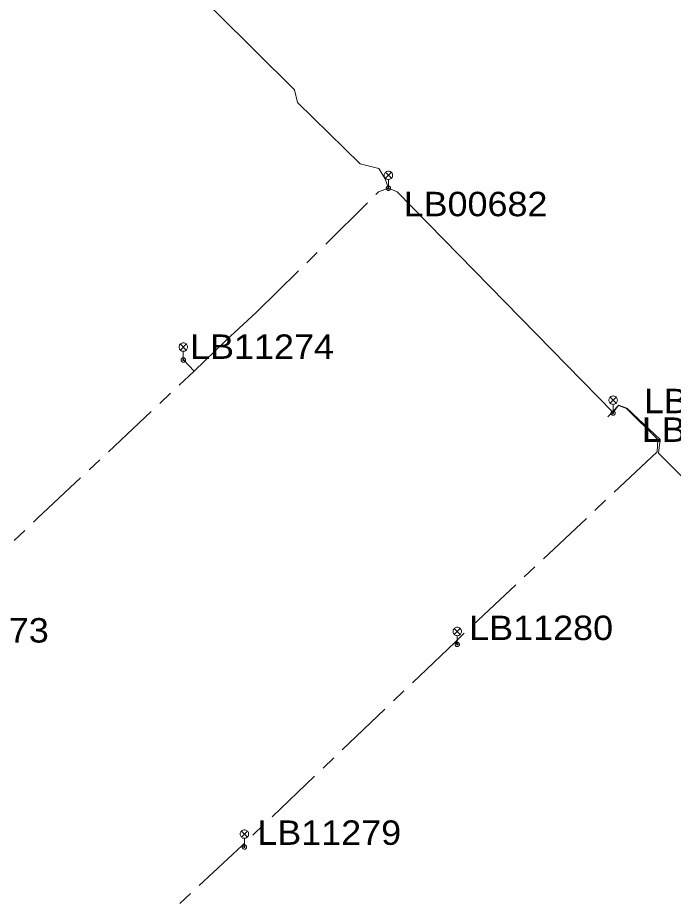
# Model space of a CAD drawing. Extents: x -688049 to -687261, y -973611 to -973038.
# Drawn here: x -687587.9 to -687529.7, y -973546.5 to -973468.5 of the extents above; entities that cross this region are included whole.
import ezdxf

# ---------------------------------------------------------------- set-up
doc = ezdxf.new("R2010")
doc.units = 0
doc.header["$LTSCALE"] = 0.87
doc.linetypes.add('LONG_DASH_SHORT_DASH', pattern=[9.9, 6, -1.2, 1.5, -1.2])
doc.layers.add('1', color=7, linetype='Continuous', lineweight=13)

msp = doc.modelspace()

# ---------------------------------------------------------------- linework, layer by layer
at = {"layer": '1'}
for p, q in [((-687555.305, -973482.205), (-687554.775, -973482.735)), ((-687555.305, -973482.735), (-687554.775, -973482.205)), ((-687555.04, -973483.62), (-687555.04, -973482.845)), ((-687573.504, -973497.442), (-687572.974, -973497.972)), ((-687573.504, -973497.972), (-687572.974, -973497.442)), ((-687573.239, -973498.857), (-687573.239, -973498.082)), ((-687535.365, -973502.155), (-687534.835, -973502.685)), ((-687535.365, -973502.685), (-687534.835, -973502.155)), ((-687535.1, -973503.57), (-687535.1, -973502.795)), ((-687549.195, -973522.675), (-687548.665, -973523.205)), ((-687549.195, -973523.205), (-687548.665, -973522.675)), ((-687548.93, -973524.09), (-687548.93, -973523.315)), ((-687568.084, -973540.652), (-687567.554, -973541.182)), ((-687568.084, -973541.182), (-687567.554, -973540.652)), ((-687567.819, -973542.067), (-687567.819, -973541.292))]:
    msp.add_line(p, q, dxfattribs=at)
at = {"layer": '1', "linetype": 'LONG_DASH_SHORT_DASH'}
for p, q in [((-687572.29, -973499.85), (-687573.23, -973498.85)), ((-687572.29, -973499.85), (-687573.23, -973498.85)), ((-687572.29, -973499.85), (-687573.23, -973498.85)), ((-687572.29, -973499.85), (-687573.23, -973498.85)), ((-687572.29, -973499.85), (-687573.23, -973498.85)), ((-687572.29, -973499.85), (-687573.23, -973498.85)), ((-687572.29, -973499.85), (-687573.23, -973498.85)), ((-687572.29, -973499.85), (-687573.23, -973498.85)), ((-687549.13, -973523.88), (-687568.01, -973541.92)), ((-687549.13, -973523.88), (-687568.01, -973541.92)), ((-687549.13, -973523.88), (-687568.01, -973541.92)), ((-687549.13, -973523.88), (-687568.01, -973541.92)), ((-687549.13, -973523.88), (-687568.01, -973541.92)), ((-687549.13, -973523.88), (-687568.01, -973541.92)), ((-687549.13, -973523.88), (-687568.01, -973541.92)), ((-687549.13, -973523.88), (-687568.01, -973541.92)), ((-687548.93, -973524.09), (-687549.13, -973523.88)), ((-687548.93, -973524.09), (-687549.13, -973523.88)), ((-687548.93, -973524.09), (-687549.13, -973523.88)), ((-687548.93, -973524.09), (-687549.13, -973523.88)), ((-687548.93, -973524.09), (-687549.13, -973523.88)), ((-687548.93, -973524.09), (-687549.13, -973523.88)), ((-687548.93, -973524.09), (-687549.13, -973523.88)), ((-687548.93, -973524.09), (-687549.13, -973523.88)), ((-687567.81, -973542.06), (-687568.01, -973541.92)), ((-687567.81, -973542.06), (-687568.01, -973541.92)), ((-687567.81, -973542.06), (-687568.01, -973541.92)), ((-687567.81, -973542.06), (-687568.01, -973541.92)), ((-687567.81, -973542.06), (-687568.01, -973541.92)), ((-687567.81, -973542.06), (-687568.01, -973541.92)), ((-687567.81, -973542.06), (-687568.01, -973541.92)), ((-687567.81, -973542.06), (-687568.01, -973541.92))]:
    msp.add_line(p, q, dxfattribs=at)
at = {"layer": '1'}
for points in [[(-687573.92, -973464.67), (-687573.727, -973464.6), (-687563.369, -973474.889), (-687563.105, -973476.008), (-687557.547, -973481.454), (-687555.888, -973481.862), (-687555.339, -973482.791), (-687555.04, -973483.62)], [(-687555.04, -973483.62), (-687554.25, -973483.935), (-687535.1, -973503.52)], [(-687535.096, -973503.52), (-687534.622, -973502.856), (-687533.88, -973503.123), (-687530.924, -973505.899), (-687531.06, -973507.111), (-687517.877, -973520.244), (-687517.442, -973520.985), (-687517.645, -973521.334)]]:
    msp.add_lwpolyline(points, dxfattribs=at)
for points in [[(-687554.665, -973482.47), (-687554.671, -973482.405), (-687554.688, -973482.342), (-687554.715, -973482.283), (-687554.753, -973482.229), (-687554.799, -973482.183), (-687554.852, -973482.145), (-687554.912, -973482.118), (-687554.975, -973482.101), (-687555.04, -973482.095), (-687555.105, -973482.101), (-687555.168, -973482.118), (-687555.228, -973482.145), (-687555.281, -973482.183), (-687555.327, -973482.229), (-687555.365, -973482.283), (-687555.392, -973482.342), (-687555.409, -973482.405), (-687555.415, -973482.47), (-687555.409, -973482.535), (-687555.392, -973482.598), (-687555.365, -973482.658), (-687555.327, -973482.711), (-687555.281, -973482.757), (-687555.228, -973482.795), (-687555.168, -973482.822), (-687555.105, -973482.839), (-687555.04, -973482.845), (-687554.975, -973482.839), (-687554.912, -973482.822), (-687554.852, -973482.795), (-687554.799, -973482.757), (-687554.753, -973482.711), (-687554.715, -973482.658), (-687554.688, -973482.598), (-687554.671, -973482.535)], [(-687554.85, -973483.62), (-687554.853, -973483.587), (-687554.861, -973483.555), (-687554.875, -973483.525), (-687554.894, -973483.498), (-687554.918, -973483.474), (-687554.945, -973483.455), (-687554.975, -973483.441), (-687555.007, -973483.433), (-687555.04, -973483.43), (-687555.073, -973483.433), (-687555.105, -973483.441), (-687555.135, -973483.455), (-687555.162, -973483.474), (-687555.186, -973483.498), (-687555.205, -973483.525), (-687555.219, -973483.555), (-687555.227, -973483.587), (-687555.23, -973483.62), (-687555.227, -973483.653), (-687555.219, -973483.685), (-687555.205, -973483.715), (-687555.186, -973483.742), (-687555.162, -973483.766), (-687555.135, -973483.785), (-687555.105, -973483.799), (-687555.073, -973483.807), (-687555.04, -973483.81), (-687555.007, -973483.807), (-687554.975, -973483.799), (-687554.945, -973483.785), (-687554.918, -973483.766), (-687554.894, -973483.742), (-687554.875, -973483.715), (-687554.861, -973483.685), (-687554.853, -973483.653)], [(-687554.99, -973483.62), (-687554.991, -973483.611), (-687554.993, -973483.603), (-687554.997, -973483.595), (-687555.002, -973483.588), (-687555.008, -973483.582), (-687555.015, -973483.577), (-687555.023, -973483.573), (-687555.031, -973483.571), (-687555.04, -973483.57), (-687555.049, -973483.571), (-687555.057, -973483.573), (-687555.065, -973483.577), (-687555.072, -973483.582), (-687555.078, -973483.588), (-687555.083, -973483.595), (-687555.087, -973483.603), (-687555.089, -973483.611), (-687555.09, -973483.62), (-687555.089, -973483.629), (-687555.087, -973483.637), (-687555.083, -973483.645), (-687555.078, -973483.652), (-687555.072, -973483.658), (-687555.065, -973483.663), (-687555.057, -973483.667), (-687555.049, -973483.669), (-687555.04, -973483.67), (-687555.031, -973483.669), (-687555.023, -973483.667), (-687555.015, -973483.663), (-687555.008, -973483.658), (-687555.002, -973483.652), (-687554.997, -973483.645), (-687554.993, -973483.637), (-687554.991, -973483.629)], [(-687572.864, -973497.707), (-687572.87, -973497.642), (-687572.887, -973497.579), (-687572.914, -973497.519), (-687572.952, -973497.466), (-687572.998, -973497.42), (-687573.052, -973497.382), (-687573.111, -973497.355), (-687573.174, -973497.338), (-687573.239, -973497.332), (-687573.304, -973497.338), (-687573.367, -973497.355), (-687573.426, -973497.382), (-687573.48, -973497.42), (-687573.526, -973497.466), (-687573.564, -973497.519), (-687573.591, -973497.579), (-687573.608, -973497.642), (-687573.614, -973497.707), (-687573.608, -973497.772), (-687573.591, -973497.835), (-687573.564, -973497.894), (-687573.526, -973497.948), (-687573.48, -973497.994), (-687573.426, -973498.032), (-687573.367, -973498.059), (-687573.304, -973498.076), (-687573.239, -973498.082), (-687573.174, -973498.076), (-687573.111, -973498.059), (-687573.052, -973498.032), (-687572.998, -973497.994), (-687572.952, -973497.948), (-687572.914, -973497.894), (-687572.887, -973497.835), (-687572.87, -973497.772)], [(-687573.049, -973498.857), (-687573.052, -973498.824), (-687573.06, -973498.792), (-687573.074, -973498.762), (-687573.093, -973498.735), (-687573.117, -973498.711), (-687573.144, -973498.692), (-687573.174, -973498.678), (-687573.206, -973498.67), (-687573.239, -973498.667), (-687573.272, -973498.67), (-687573.304, -973498.678), (-687573.334, -973498.692), (-687573.361, -973498.711), (-687573.385, -973498.735), (-687573.404, -973498.762), (-687573.418, -973498.792), (-687573.426, -973498.824), (-687573.429, -973498.857), (-687573.426, -973498.89), (-687573.418, -973498.922), (-687573.404, -973498.952), (-687573.385, -973498.979), (-687573.361, -973499.003), (-687573.334, -973499.022), (-687573.304, -973499.036), (-687573.272, -973499.044), (-687573.239, -973499.047), (-687573.206, -973499.044), (-687573.174, -973499.036), (-687573.144, -973499.022), (-687573.117, -973499.003), (-687573.093, -973498.979), (-687573.074, -973498.952), (-687573.06, -973498.922), (-687573.052, -973498.89)], [(-687573.189, -973498.857), (-687573.19, -973498.848), (-687573.192, -973498.84), (-687573.196, -973498.832), (-687573.201, -973498.825), (-687573.207, -973498.819), (-687573.214, -973498.814), (-687573.222, -973498.81), (-687573.23, -973498.808), (-687573.239, -973498.807), (-687573.248, -973498.808), (-687573.256, -973498.81), (-687573.264, -973498.814), (-687573.271, -973498.819), (-687573.277, -973498.825), (-687573.282, -973498.832), (-687573.286, -973498.84), (-687573.288, -973498.848), (-687573.289, -973498.857), (-687573.288, -973498.866), (-687573.286, -973498.874), (-687573.282, -973498.882), (-687573.277, -973498.889), (-687573.271, -973498.895), (-687573.264, -973498.9), (-687573.256, -973498.904), (-687573.248, -973498.906), (-687573.239, -973498.907), (-687573.23, -973498.906), (-687573.222, -973498.904), (-687573.214, -973498.9), (-687573.207, -973498.895), (-687573.201, -973498.889), (-687573.196, -973498.882), (-687573.192, -973498.874), (-687573.19, -973498.866)], [(-687534.725, -973502.42), (-687534.731, -973502.355), (-687534.748, -973502.292), (-687534.775, -973502.232), (-687534.813, -973502.179), (-687534.859, -973502.133), (-687534.912, -973502.095), (-687534.972, -973502.068), (-687535.035, -973502.051), (-687535.1, -973502.045), (-687535.165, -973502.051), (-687535.228, -973502.068), (-687535.288, -973502.095), (-687535.341, -973502.133), (-687535.387, -973502.179), (-687535.425, -973502.232), (-687535.452, -973502.292), (-687535.469, -973502.355), (-687535.475, -973502.42), (-687535.469, -973502.485), (-687535.452, -973502.548), (-687535.425, -973502.607), (-687535.387, -973502.661), (-687535.341, -973502.707), (-687535.288, -973502.745), (-687535.228, -973502.772), (-687535.165, -973502.789), (-687535.1, -973502.795), (-687535.035, -973502.789), (-687534.972, -973502.772), (-687534.912, -973502.745), (-687534.859, -973502.707), (-687534.813, -973502.661), (-687534.775, -973502.607), (-687534.748, -973502.548), (-687534.731, -973502.485)], [(-687534.91, -973503.57), (-687534.913, -973503.537), (-687534.921, -973503.505), (-687534.935, -973503.475), (-687534.954, -973503.448), (-687534.978, -973503.424), (-687535.005, -973503.405), (-687535.035, -973503.391), (-687535.067, -973503.383), (-687535.1, -973503.38), (-687535.133, -973503.383), (-687535.165, -973503.391), (-687535.195, -973503.405), (-687535.222, -973503.424), (-687535.246, -973503.448), (-687535.265, -973503.475), (-687535.279, -973503.505), (-687535.287, -973503.537), (-687535.29, -973503.57), (-687535.287, -973503.603), (-687535.279, -973503.635), (-687535.265, -973503.665), (-687535.246, -973503.692), (-687535.222, -973503.716), (-687535.195, -973503.735), (-687535.165, -973503.749), (-687535.133, -973503.757), (-687535.1, -973503.76), (-687535.067, -973503.757), (-687535.035, -973503.749), (-687535.005, -973503.735), (-687534.978, -973503.716), (-687534.954, -973503.692), (-687534.935, -973503.665), (-687534.921, -973503.635), (-687534.913, -973503.603)], [(-687535.05, -973503.57), (-687535.051, -973503.561), (-687535.053, -973503.553), (-687535.057, -973503.545), (-687535.062, -973503.538), (-687535.068, -973503.532), (-687535.075, -973503.527), (-687535.083, -973503.523), (-687535.091, -973503.521), (-687535.1, -973503.52), (-687535.109, -973503.521), (-687535.117, -973503.523), (-687535.125, -973503.527), (-687535.132, -973503.532), (-687535.138, -973503.538), (-687535.143, -973503.545), (-687535.147, -973503.553), (-687535.149, -973503.561), (-687535.15, -973503.57), (-687535.149, -973503.579), (-687535.147, -973503.587), (-687535.143, -973503.595), (-687535.138, -973503.602), (-687535.132, -973503.608), (-687535.125, -973503.613), (-687535.117, -973503.617), (-687535.109, -973503.619), (-687535.1, -973503.62), (-687535.091, -973503.619), (-687535.083, -973503.617), (-687535.075, -973503.613), (-687535.068, -973503.608), (-687535.062, -973503.602), (-687535.057, -973503.595), (-687535.053, -973503.587), (-687535.051, -973503.579)], [(-687548.555, -973522.94), (-687548.561, -973522.875), (-687548.578, -973522.812), (-687548.605, -973522.753), (-687548.643, -973522.699), (-687548.689, -973522.653), (-687548.742, -973522.615), (-687548.802, -973522.588), (-687548.865, -973522.571), (-687548.93, -973522.565), (-687548.995, -973522.571), (-687549.058, -973522.588), (-687549.118, -973522.615), (-687549.171, -973522.653), (-687549.217, -973522.699), (-687549.255, -973522.753), (-687549.282, -973522.812), (-687549.299, -973522.875), (-687549.305, -973522.94), (-687549.299, -973523.005), (-687549.282, -973523.068), (-687549.255, -973523.128), (-687549.217, -973523.181), (-687549.171, -973523.227), (-687549.118, -973523.265), (-687549.058, -973523.292), (-687548.995, -973523.309), (-687548.93, -973523.315), (-687548.865, -973523.309), (-687548.802, -973523.292), (-687548.742, -973523.265), (-687548.689, -973523.227), (-687548.643, -973523.181), (-687548.605, -973523.128), (-687548.578, -973523.068), (-687548.561, -973523.005)], [(-687548.74, -973524.09), (-687548.743, -973524.057), (-687548.751, -973524.025), (-687548.765, -973523.995), (-687548.784, -973523.968), (-687548.808, -973523.944), (-687548.835, -973523.925), (-687548.865, -973523.911), (-687548.897, -973523.903), (-687548.93, -973523.9), (-687548.963, -973523.903), (-687548.995, -973523.911), (-687549.025, -973523.925), (-687549.052, -973523.944), (-687549.076, -973523.968), (-687549.095, -973523.995), (-687549.109, -973524.025), (-687549.117, -973524.057), (-687549.12, -973524.09), (-687549.117, -973524.123), (-687549.109, -973524.155), (-687549.095, -973524.185), (-687549.076, -973524.212), (-687549.052, -973524.236), (-687549.025, -973524.255), (-687548.995, -973524.269), (-687548.963, -973524.277), (-687548.93, -973524.28), (-687548.897, -973524.277), (-687548.865, -973524.269), (-687548.835, -973524.255), (-687548.808, -973524.236), (-687548.784, -973524.212), (-687548.765, -973524.185), (-687548.751, -973524.155), (-687548.743, -973524.123)], [(-687548.88, -973524.09), (-687548.881, -973524.081), (-687548.883, -973524.073), (-687548.887, -973524.065), (-687548.892, -973524.058), (-687548.898, -973524.052), (-687548.905, -973524.047), (-687548.913, -973524.043), (-687548.921, -973524.041), (-687548.93, -973524.04), (-687548.939, -973524.041), (-687548.947, -973524.043), (-687548.955, -973524.047), (-687548.962, -973524.052), (-687548.968, -973524.058), (-687548.973, -973524.065), (-687548.977, -973524.073), (-687548.979, -973524.081), (-687548.98, -973524.09), (-687548.979, -973524.099), (-687548.977, -973524.107), (-687548.973, -973524.115), (-687548.968, -973524.122), (-687548.962, -973524.128), (-687548.955, -973524.133), (-687548.947, -973524.137), (-687548.939, -973524.139), (-687548.93, -973524.14), (-687548.921, -973524.139), (-687548.913, -973524.137), (-687548.905, -973524.133), (-687548.898, -973524.128), (-687548.892, -973524.122), (-687548.887, -973524.115), (-687548.883, -973524.107), (-687548.881, -973524.099)], [(-687567.444, -973540.917), (-687567.45, -973540.852), (-687567.467, -973540.789), (-687567.494, -973540.73), (-687567.532, -973540.676), (-687567.578, -973540.63), (-687567.632, -973540.592), (-687567.691, -973540.565), (-687567.754, -973540.548), (-687567.819, -973540.542), (-687567.884, -973540.548), (-687567.947, -973540.565), (-687568.006, -973540.592), (-687568.06, -973540.63), (-687568.106, -973540.676), (-687568.144, -973540.73), (-687568.171, -973540.789), (-687568.188, -973540.852), (-687568.194, -973540.917), (-687568.188, -973540.982), (-687568.171, -973541.045), (-687568.144, -973541.105), (-687568.106, -973541.158), (-687568.06, -973541.204), (-687568.006, -973541.242), (-687567.947, -973541.269), (-687567.884, -973541.286), (-687567.819, -973541.292), (-687567.754, -973541.286), (-687567.691, -973541.269), (-687567.632, -973541.242), (-687567.578, -973541.204), (-687567.532, -973541.158), (-687567.494, -973541.105), (-687567.467, -973541.045), (-687567.45, -973540.982)], [(-687567.629, -973542.067), (-687567.632, -973542.034), (-687567.64, -973542.002), (-687567.654, -973541.972), (-687567.673, -973541.945), (-687567.697, -973541.921), (-687567.724, -973541.902), (-687567.754, -973541.888), (-687567.786, -973541.88), (-687567.819, -973541.877), (-687567.852, -973541.88), (-687567.884, -973541.888), (-687567.914, -973541.902), (-687567.941, -973541.921), (-687567.965, -973541.945), (-687567.984, -973541.972), (-687567.998, -973542.002), (-687568.006, -973542.034), (-687568.009, -973542.067), (-687568.006, -973542.1), (-687567.998, -973542.132), (-687567.984, -973542.162), (-687567.965, -973542.189), (-687567.941, -973542.213), (-687567.914, -973542.232), (-687567.884, -973542.246), (-687567.852, -973542.254), (-687567.819, -973542.257), (-687567.786, -973542.254), (-687567.754, -973542.246), (-687567.724, -973542.232), (-687567.697, -973542.213), (-687567.673, -973542.189), (-687567.654, -973542.162), (-687567.64, -973542.132), (-687567.632, -973542.1)], [(-687567.769, -973542.067), (-687567.77, -973542.058), (-687567.772, -973542.05), (-687567.776, -973542.042), (-687567.781, -973542.035), (-687567.787, -973542.029), (-687567.794, -973542.024), (-687567.802, -973542.02), (-687567.81, -973542.018), (-687567.819, -973542.017), (-687567.828, -973542.018), (-687567.836, -973542.02), (-687567.844, -973542.024), (-687567.851, -973542.029), (-687567.857, -973542.035), (-687567.862, -973542.042), (-687567.866, -973542.05), (-687567.868, -973542.058), (-687567.869, -973542.067), (-687567.868, -973542.076), (-687567.866, -973542.084), (-687567.862, -973542.092), (-687567.857, -973542.099), (-687567.851, -973542.105), (-687567.844, -973542.11), (-687567.836, -973542.114), (-687567.828, -973542.116), (-687567.819, -973542.117), (-687567.81, -973542.116), (-687567.802, -973542.114), (-687567.794, -973542.11), (-687567.787, -973542.105), (-687567.781, -973542.099), (-687567.776, -973542.092), (-687567.772, -973542.084), (-687567.77, -973542.076)]]:
    msp.add_lwpolyline(points, close=True, dxfattribs=at)
at = {"layer": '1', "linetype": 'LONG_DASH_SHORT_DASH'}
for points in [[(-687572.29, -973499.85), (-687569.47, -973497.12), (-687566.74, -973494.62), (-687555.92, -973483.95), (-687555.04, -973483.62)], [(-687572.29, -973499.85), (-687569.47, -973497.12), (-687566.74, -973494.62), (-687555.92, -973483.95), (-687555.04, -973483.62)], [(-687572.29, -973499.85), (-687569.47, -973497.12), (-687566.74, -973494.62), (-687555.92, -973483.95), (-687555.04, -973483.62)], [(-687572.29, -973499.85), (-687569.47, -973497.12), (-687566.74, -973494.62), (-687555.92, -973483.95), (-687555.04, -973483.62)], [(-687572.29, -973499.85), (-687569.47, -973497.12), (-687566.74, -973494.62), (-687555.92, -973483.95), (-687555.04, -973483.62)], [(-687572.29, -973499.85), (-687569.47, -973497.12), (-687566.74, -973494.62), (-687555.92, -973483.95), (-687555.04, -973483.62)], [(-687572.29, -973499.85), (-687569.47, -973497.12), (-687566.74, -973494.62), (-687555.92, -973483.95), (-687555.04, -973483.62)], [(-687572.29, -973499.85), (-687569.47, -973497.12), (-687566.74, -973494.62), (-687555.92, -973483.95), (-687555.04, -973483.62)], [(-687599.14, -973524.63), (-687599.01, -973525.14), (-687586.17, -973512.89), (-687572.29, -973499.85)], [(-687599.14, -973524.63), (-687599.01, -973525.14), (-687586.17, -973512.89), (-687572.29, -973499.85)], [(-687599.14, -973524.63), (-687599.01, -973525.14), (-687586.17, -973512.89), (-687572.29, -973499.85)], [(-687599.14, -973524.63), (-687599.01, -973525.14), (-687586.17, -973512.89), (-687572.29, -973499.85)], [(-687599.14, -973524.63), (-687599.01, -973525.14), (-687586.17, -973512.89), (-687572.29, -973499.85)], [(-687599.14, -973524.63), (-687599.01, -973525.14), (-687586.17, -973512.89), (-687572.29, -973499.85)], [(-687599.14, -973524.63), (-687599.01, -973525.14), (-687586.17, -973512.89), (-687572.29, -973499.85)], [(-687599.14, -973524.63), (-687599.01, -973525.14), (-687586.17, -973512.89), (-687572.29, -973499.85)], [(-687535.58, -973503.9), (-687534.62, -973502.9), (-687533.9, -973503.16), (-687531.12, -973505.91), (-687531.2, -973507.01), (-687549.13, -973523.88)], [(-687535.58, -973503.9), (-687534.62, -973502.9), (-687533.9, -973503.16), (-687531.12, -973505.91), (-687531.2, -973507.01), (-687549.13, -973523.88)], [(-687535.58, -973503.9), (-687534.62, -973502.9), (-687533.9, -973503.16), (-687531.12, -973505.91), (-687531.2, -973507.01), (-687549.13, -973523.88)], [(-687535.58, -973503.9), (-687534.62, -973502.9), (-687533.9, -973503.16), (-687531.12, -973505.91), (-687531.2, -973507.01), (-687549.13, -973523.88)], [(-687535.58, -973503.9), (-687534.62, -973502.9), (-687533.9, -973503.16), (-687531.12, -973505.91), (-687531.2, -973507.01), (-687549.13, -973523.88)], [(-687535.58, -973503.9), (-687534.62, -973502.9), (-687533.9, -973503.16), (-687531.12, -973505.91), (-687531.2, -973507.01), (-687549.13, -973523.88)], [(-687535.58, -973503.9), (-687534.62, -973502.9), (-687533.9, -973503.16), (-687531.12, -973505.91), (-687531.2, -973507.01), (-687549.13, -973523.88)], [(-687535.58, -973503.9), (-687534.62, -973502.9), (-687533.9, -973503.16), (-687531.12, -973505.91), (-687531.2, -973507.01), (-687549.13, -973523.88)], [(-687568.01, -973541.92), (-687578.1, -973551.33), (-687587.04, -973559.73)], [(-687568.01, -973541.92), (-687578.1, -973551.33), (-687587.04, -973559.73)], [(-687568.01, -973541.92), (-687578.1, -973551.33), (-687587.04, -973559.73)], [(-687568.01, -973541.92), (-687578.1, -973551.33), (-687587.04, -973559.73)], [(-687568.01, -973541.92), (-687578.1, -973551.33), (-687587.04, -973559.73)], [(-687568.01, -973541.92), (-687578.1, -973551.33), (-687587.04, -973559.73)], [(-687568.01, -973541.92), (-687578.1, -973551.33), (-687587.04, -973559.73)], [(-687568.01, -973541.92), (-687578.1, -973551.33), (-687587.04, -973559.73)]]:
    msp.add_lwpolyline(points, dxfattribs=at)

# ---------------------------------------------------------------- texts
at = {"layer": '1', "width": 1.1}
for s, height, p in [('LB00682', 2.167, (-687553.69, -973486.102)), ('LB11274', 2.168, (-687572.64, -973498.758)), ('LB00681', 2.167, (-687532.369, -973503.577)), ('LB59249', 2.168, (-687532.548, -973506.12)), ('LB11273', 2.168, (-687597.944, -973523.926)), ('LB11280', 2.168, (-687547.873, -973523.706)), ('LB11279', 2.168, (-687566.677, -973541.874))]:
    msp.add_text(s, height=height, dxfattribs=at).set_placement(p)

doc.saveas('drawing.dxf')
